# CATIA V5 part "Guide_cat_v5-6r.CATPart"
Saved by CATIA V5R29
Part number: Guide
Bounding box of the stored display mesh (mm): x -5 to 5, y -5 to 5, z -25 to 25
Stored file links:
  C:\Users\CADCIM 00\Desktop\New folder (2)\c16\New folder\Cam Follower mechanism\Guide_cat_v5-6r.CATPart
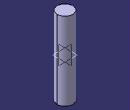
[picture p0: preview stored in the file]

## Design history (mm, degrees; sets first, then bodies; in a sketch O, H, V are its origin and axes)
Body1 (main body)
  Sketch1 on xy-plane, origin (0, 0, 0), H (1, 0, 0), V (0, 1, 0)
    circle A1 centre (0, 0) radius 5
    radius A1 = 5
  Pad1: profile Sketch1, direction (0, 0, 1), length 25, mirrored extent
